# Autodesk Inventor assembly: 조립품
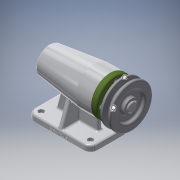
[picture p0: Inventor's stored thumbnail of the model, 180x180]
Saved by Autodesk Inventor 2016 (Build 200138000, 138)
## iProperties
Created: 2018-09
Part Number: 조립품
Material: 일반
Document SubType Name: Assembly
Designer: 3sil_cad018
Author: 3sil_cad018
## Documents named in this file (12)
- C:\Users\3sil_cad018\Desktop\480907V1008\조립품.iam
- C:\Users\3sil_cad018\Desktop\480907V1008\본체.ipt
- C:\Users\3sil_cad018\Desktop\480907V1008\V벨트풀리.ipt
- C:\Users\3sil_cad018\Desktop\480907V1008\멈춤나사 M3.ipt
- C:\Users\3sil_cad018\Desktop\480907V1008\베어링 6004.ipt
- C:\Users\3sil_cad018\Desktop\480907V1008\베어링 51202.ipt
- C:\Users\3sil_cad018\Desktop\480907V1008\볼트 M4.ipt
- C:\Users\3sil_cad018\Desktop\480907V1008\어댑터슬리브.ipt
- C:\Users\3sil_cad018\Desktop\480907V1008\오일 실.ipt
- C:\Users\3sil_cad018\Desktop\480907V1008\축.ipt
- C:\Users\3sil_cad018\Desktop\480907V1008\커버.ipt
- C:\Users\3sil_cad018\Desktop\480907V1008\키 5 x 5 x 16.ipt
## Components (1 placed, 1 different names)
1. V벨트풀리:1 — 각도:2
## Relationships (1: Angle 1)
- 각도:2 [Angle]: V벨트풀리:1
